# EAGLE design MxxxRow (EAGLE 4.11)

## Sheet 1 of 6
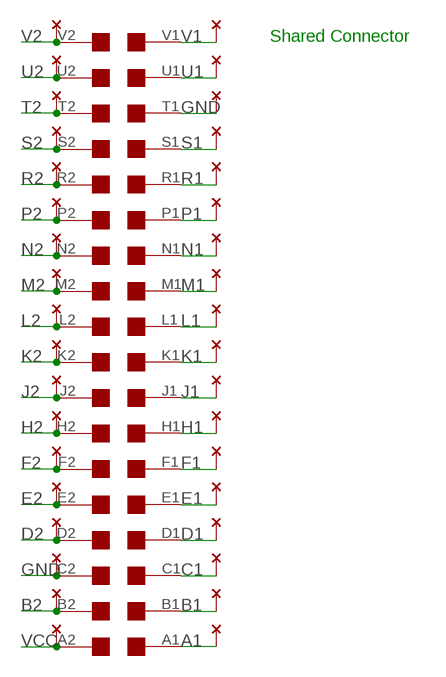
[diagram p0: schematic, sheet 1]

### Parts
U$1  EDGE-2  [EDGE-CON2]
U$4  THRU-HOLE2  [THRU-HOLEB]

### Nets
A1: U$1.A1 U$4.A2 ; also sheet 2,3,4,5,6
B1: U$1.B1 U$4.B2 ; also sheet 2,3,4,5,6
B2: U$1.B2 U$4.B1
C1: U$1.C1 U$4.C2 ; also sheet 2,3,4,5,6
D1: U$1.D1 U$4.D2 ; also sheet 2,3,4,5,6
D2: U$1.D2 U$4.D1 ; also sheet 2,3,4,5,6
E1: U$1.E1 U$4.E2 ; also sheet 2,3,4,5
E2: U$1.E2 U$4.E1 ; also sheet 2,3,4,5,6
F1: U$1.F1 U$4.F2 ; also sheet 2,3,4,5,6
F2: U$1.F2 U$4.F1 ; also sheet 2,3,4,5,6
GND [Power]: U$1.C2 U$1.T1 U$4.C1 U$4.T2 ; also sheet 2,3,4,5,6
H1: U$1.H1 U$4.H2 ; also sheet 2,3,4,5,6
H2: U$1.H2 U$4.H1 ; also sheet 2,3,4,5,6
J1: U$1.J1 U$4.J2 ; also sheet 2,3,4,5,6
J2: U$1.J2 U$4.J1 ; also sheet 2,3,4,5,6
K1: U$1.K1 U$4.K2 ; also sheet 2,3,4,5,6
K2: U$1.K2 U$4.K1 ; also sheet 2,3,4,5,6
L1: U$1.L1 U$4.L2 ; also sheet 2,3,4,5
L2: U$1.L2 U$4.L1 ; also sheet 2,3,4,5,6
M1: U$1.M1 U$4.M2 ; also sheet 2,3,4,5,6
M2: U$1.M2 U$4.M1 ; also sheet 2,3,4,5,6
N1: U$1.N1 U$4.N2 ; also sheet 2,3,4,5,6
N2: U$1.N2 U$4.N1 ; also sheet 2,3,4,5,6
P1: U$1.P1 U$4.P2 ; also sheet 2,3,4,5,6
P2: U$1.P2 U$4.P1 ; also sheet 2,3,4,5,6
R1: U$1.R1 U$4.R2 ; also sheet 2,3,4,5,6
R2: U$1.R2 U$4.R1 ; also sheet 2,3,4,5,6
S1: U$1.S1 U$4.S2 ; also sheet 2,3,4,5
S2: U$1.S2 U$4.S1 ; also sheet 2,3,4,5,6
T2: U$1.T2 U$4.T1 ; also sheet 2,3,4,5,6
U1: U$1.U1 U$4.U2 ; also sheet 2,3,4
U2: U$1.U2 U$4.U1 ; also sheet 2,3,4,5,6
V1: U$1.V1 U$4.V2 ; also sheet 2,3,4
V2: U$1.V2 U$4.V1 ; also sheet 2,3,4,5,6
VCC [Power]: U$1.A2 U$4.A1 ; also sheet 2,3,4,5,6

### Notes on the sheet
- Shared Connector

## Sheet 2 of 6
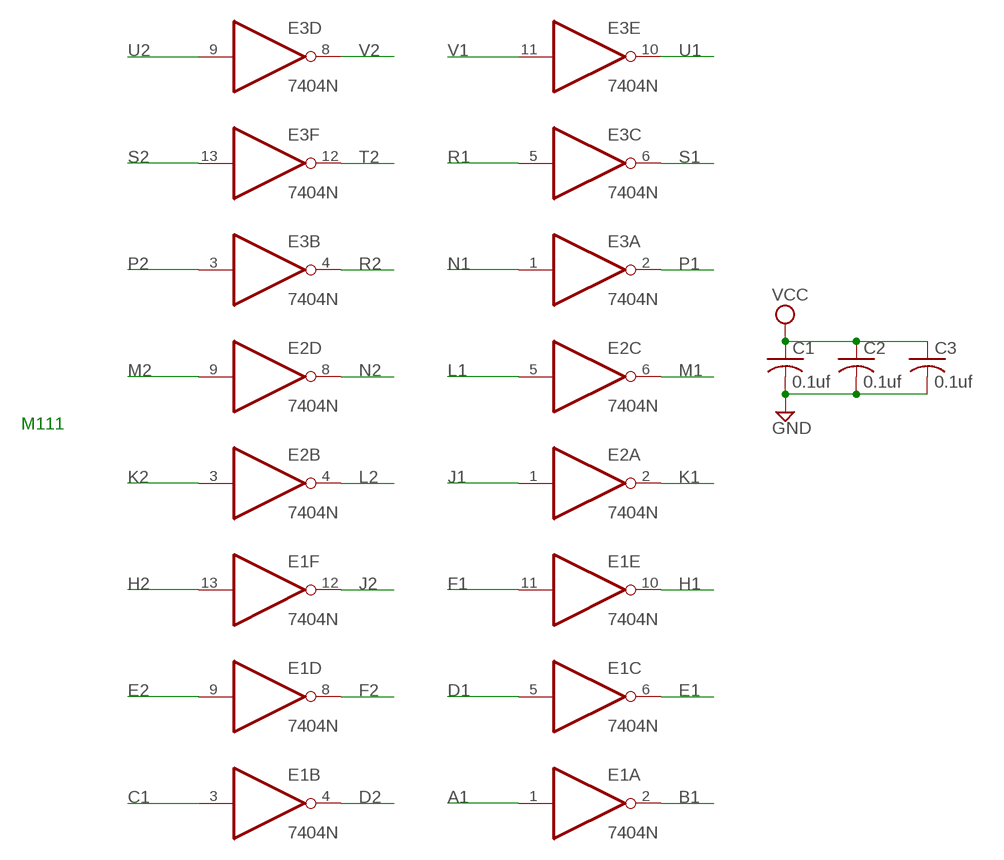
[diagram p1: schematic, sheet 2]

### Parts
C1  0.1uf  C-US050-025X075  [C050-025X075]
C2  0.1uf  C-US050-025X075  [C050-025X075]
C3  0.1uf  C-US050-025X075  [C050-025X075]
E1  7404N  [DIL14]
E2  7404N  [DIL14]
E3  7404N  [DIL14]

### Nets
A1: E1.1(A:I) ; also sheet 1,3,4,5,6
B1: E1.2(A:O) ; also sheet 1,3,4,5,6
C1: E1.3(B:I) ; also sheet 1,3,4,5,6
D1: E1.5(C:I) ; also sheet 1,3,4,5,6
D2: E1.4(B:O) ; also sheet 1,3,4,5,6
E1: E1.6(C:O) ; also sheet 1,3,4,5
E2: E1.9(D:I) ; also sheet 1,3,4,5,6
F1: E1.11(E:I) ; also sheet 1,3,4,5,6
F2: E1.8(D:O) ; also sheet 1,3,4,5,6
GND [Power]: C1.2 C2.2 C3.2 ; also sheet 1,3,4,5,6
H1: E1.10(E:O) ; also sheet 1,3,4,5,6
H2: E1.13(F:I) ; also sheet 1,3,4,5,6
J1: E2.1(A:I) ; also sheet 1,3,4,5,6
J2: E1.12(F:O) ; also sheet 1,3,4,5,6
K1: E2.2(A:O) ; also sheet 1,3,4,5,6
K2: E2.3(B:I) ; also sheet 1,3,4,5,6
L1: E2.5(C:I) ; also sheet 1,3,4,5
L2: E2.4(B:O) ; also sheet 1,3,4,5,6
M1: E2.6(C:O) ; also sheet 1,3,4,5,6
M2: E2.9(D:I) ; also sheet 1,3,4,5,6
N1: E3.1(A:I) ; also sheet 1,3,4,5,6
N2: E2.8(D:O) ; also sheet 1,3,4,5,6
P1: E3.2(A:O) ; also sheet 1,3,4,5,6
P2: E3.3(B:I) ; also sheet 1,3,4,5,6
R1: E3.5(C:I) ; also sheet 1,3,4,5,6
R2: E3.4(B:O) ; also sheet 1,3,4,5,6
S1: E3.6(C:O) ; also sheet 1,3,4,5
S2: E3.13(F:I) ; also sheet 1,3,4,5,6
T2: E3.12(F:O) ; also sheet 1,3,4,5,6
U1: E3.10(E:O) ; also sheet 1,3,4
U2: E3.9(D:I) ; also sheet 1,3,4,5,6
V1: E3.11(E:I) ; also sheet 1,3,4
V2: E3.8(D:O) ; also sheet 1,3,4,5,6
VCC [Power]: C1.1 C2.1 C3.1 ; also sheet 1,3,4,5,6
Unconnected: E2.10(E:O) E2.11(E:I) E2.12(F:O) E2.13(F:I)

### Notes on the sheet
- M111

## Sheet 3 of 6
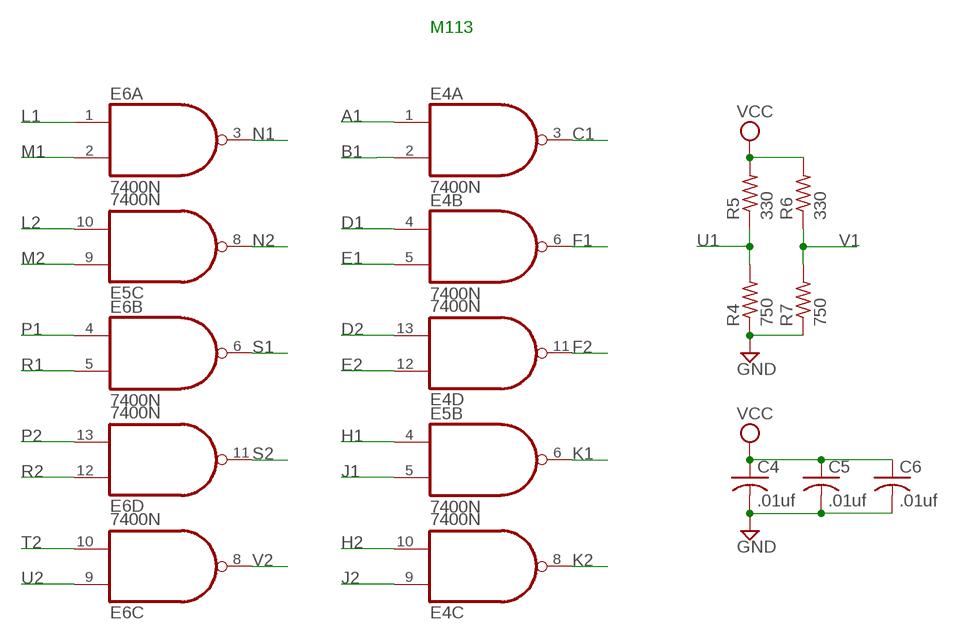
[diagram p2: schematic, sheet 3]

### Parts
C4  .01uf  C-US050-025X075  [C050-025X075]
C5  .01uf  C-US050-025X075  [C050-025X075]
C6  .01uf  C-US050-025X075  [C050-025X075]
E4  7400N  [DIL14]
E5  7400N  [DIL14]
E6  7400N  [DIL14]
R4  750  R-US_0207/10  [0207/10]
R5  330  R-US_0207/10  [0207/10]
R6  330  R-US_0207/10  [0207/10]
R7  750  R-US_0207/10  [0207/10]

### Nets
A1: E4.1(A:I0) ; also sheet 1,2,4,5,6
B1: E4.2(A:I1) ; also sheet 1,2,4,5,6
C1: E4.3(A:O) ; also sheet 1,2,4,5,6
D1: E4.4(B:I0) ; also sheet 1,2,4,5,6
D2: E4.13(D:I1) ; also sheet 1,2,4,5,6
E1: E4.5(B:I1) ; also sheet 1,2,4,5
E2: E4.12(D:I0) ; also sheet 1,2,4,5,6
F1: E4.6(B:O) ; also sheet 1,2,4,5,6
F2: E4.11(D:O) ; also sheet 1,2,4,5,6
GND [Power]: C4.2 C5.2 C6.2 R4.1 R7.1 ; also sheet 1,2,4,5,6
H1: E5.4(B:I0) ; also sheet 1,2,4,5,6
H2: E4.10(C:I1) ; also sheet 1,2,4,5,6
J1: E5.5(B:I1) ; also sheet 1,2,4,5,6
J2: E4.9(C:I0) ; also sheet 1,2,4,5,6
K1: E5.6(B:O) ; also sheet 1,2,4,5,6
K2: E4.8(C:O) ; also sheet 1,2,4,5,6
L1: E6.1(A:I0) ; also sheet 1,2,4,5
L2: E5.10(C:I1) ; also sheet 1,2,4,5,6
M1: E6.2(A:I1) ; also sheet 1,2,4,5,6
M2: E5.9(C:I0) ; also sheet 1,2,4,5,6
N1: E6.3(A:O) ; also sheet 1,2,4,5,6
N2: E5.8(C:O) ; also sheet 1,2,4,5,6
P1: E6.4(B:I0) ; also sheet 1,2,4,5,6
P2: E6.13(D:I1) ; also sheet 1,2,4,5,6
R1: E6.5(B:I1) ; also sheet 1,2,4,5,6
R2: E6.12(D:I0) ; also sheet 1,2,4,5,6
S1: E6.6(B:O) ; also sheet 1,2,4,5
S2: E6.11(D:O) ; also sheet 1,2,4,5,6
T2: E6.10(C:I1) ; also sheet 1,2,4,5,6
U1: R4.2 R5.1 ; also sheet 1,2,4
U2: E6.9(C:I0) ; also sheet 1,2,4,5,6
V1: R6.1 R7.2 ; also sheet 1,2,4
V2: E6.8(C:O) ; also sheet 1,2,4,5,6
VCC [Power]: C4.1 C5.1 C6.1 R5.2 R6.2 ; also sheet 1,2,4,5,6
Unconnected: E5.1(A:I0) E5.2(A:I1) E5.3(A:O) E5.11(D:O) E5.12(D:I0) E5.13(D:I1)

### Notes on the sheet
- M113

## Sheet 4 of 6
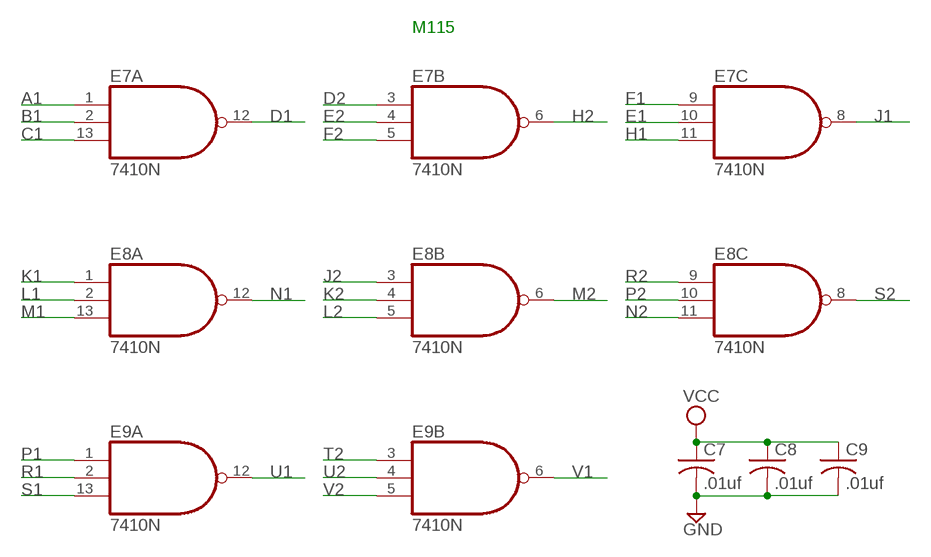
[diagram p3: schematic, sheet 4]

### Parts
C7  .01uf  C-US050-025X075  [C050-025X075]
C8  .01uf  C-US050-025X075  [C050-025X075]
C9  .01uf  C-US050-025X075  [C050-025X075]
E7  7410N  [DIL14]
E8  7410N  [DIL14]
E9  7410N  [DIL14]

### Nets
A1: E7.1(A:I0) ; also sheet 1,2,3,5,6
B1: E7.2(A:I1) ; also sheet 1,2,3,5,6
C1: E7.13(A:I2) ; also sheet 1,2,3,5,6
D1: E7.12(A:O) ; also sheet 1,2,3,5,6
D2: E7.3(B:I0) ; also sheet 1,2,3,5,6
E1: E7.10(C:I1) ; also sheet 1,2,3,5
E2: E7.4(B:I1) ; also sheet 1,2,3,5,6
F1: E7.9(C:I0) ; also sheet 1,2,3,5,6
F2: E7.5(B:I2) ; also sheet 1,2,3,5,6
GND [Power]: C7.2 C8.2 C9.2 ; also sheet 1,2,3,5,6
H1: E7.11(C:I2) ; also sheet 1,2,3,5,6
H2: E7.6(B:O) ; also sheet 1,2,3,5,6
J1: E7.8(C:O) ; also sheet 1,2,3,5,6
J2: E8.3(B:I0) ; also sheet 1,2,3,5,6
K1: E8.1(A:I0) ; also sheet 1,2,3,5,6
K2: E8.4(B:I1) ; also sheet 1,2,3,5,6
L1: E8.2(A:I1) ; also sheet 1,2,3,5
L2: E8.5(B:I2) ; also sheet 1,2,3,5,6
M1: E8.13(A:I2) ; also sheet 1,2,3,5,6
M2: E8.6(B:O) ; also sheet 1,2,3,5,6
N1: E8.12(A:O) ; also sheet 1,2,3,5,6
N2: E8.11(C:I2) ; also sheet 1,2,3,5,6
P1: E9.1(A:I0) ; also sheet 1,2,3,5,6
P2: E8.10(C:I1) ; also sheet 1,2,3,5,6
R1: E9.2(A:I1) ; also sheet 1,2,3,5,6
R2: E8.9(C:I0) ; also sheet 1,2,3,5,6
S1: E9.13(A:I2) ; also sheet 1,2,3,5
S2: E8.8(C:O) ; also sheet 1,2,3,5,6
T2: E9.3(B:I0) ; also sheet 1,2,3,5,6
U1: E9.12(A:O) ; also sheet 1,2,3
U2: E9.4(B:I1) ; also sheet 1,2,3,5,6
V1: E9.6(B:O) ; also sheet 1,2,3
V2: E9.5(B:I2) ; also sheet 1,2,3,5,6
VCC [Power]: C7.1 C8.1 C9.1 ; also sheet 1,2,3,5,6
Unconnected: E9.8(C:O) E9.9(C:I0) E9.10(C:I1) E9.11(C:I2)

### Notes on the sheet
- M115

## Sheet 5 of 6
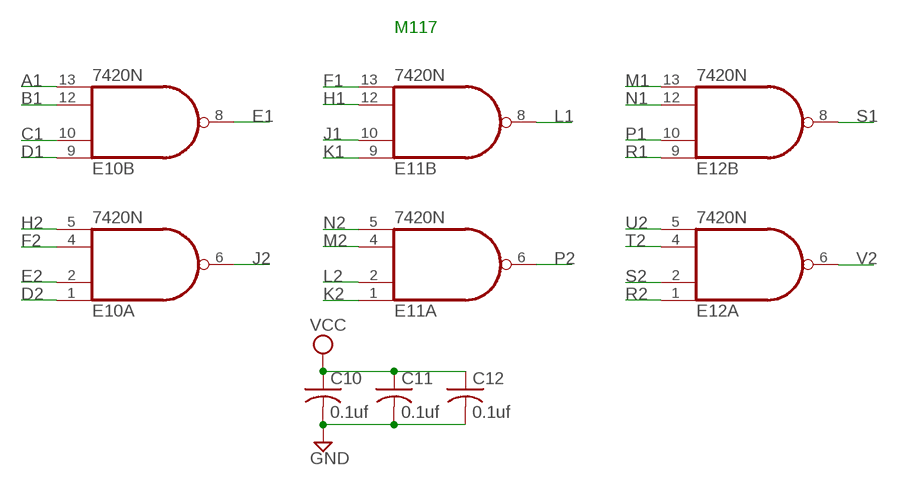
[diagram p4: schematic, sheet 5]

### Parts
C10  0.1uf  C-US050-025X075  [C050-025X075]
C11  0.1uf  C-US050-025X075  [C050-025X075]
C12  0.1uf  C-US050-025X075  [C050-025X075]
E10  7420N  74S20N  [DIL14]
E11  7420N  74S20N  [DIL14]
E12  7420N  74S20N  [DIL14]

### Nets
A1: E10.13(B:I3) ; also sheet 1,2,3,4,6
B1: E10.12(B:I2) ; also sheet 1,2,3,4,6
C1: E10.10(B:I1) ; also sheet 1,2,3,4,6
D1: E10.9(B:I0) ; also sheet 1,2,3,4,6
D2: E10.1(A:I0) ; also sheet 1,2,3,4,6
E1: E10.8(B:O) ; also sheet 1,2,3,4
E2: E10.2(A:I1) ; also sheet 1,2,3,4,6
F1: E11.13(B:I3) ; also sheet 1,2,3,4,6
F2: E10.4(A:I2) ; also sheet 1,2,3,4,6
GND [Power]: C10.2 C11.2 C12.2 ; also sheet 1,2,3,4,6
H1: E11.12(B:I2) ; also sheet 1,2,3,4,6
H2: E10.5(A:I3) ; also sheet 1,2,3,4,6
J1: E11.10(B:I1) ; also sheet 1,2,3,4,6
J2: E10.6(A:O) ; also sheet 1,2,3,4,6
K1: E11.9(B:I0) ; also sheet 1,2,3,4,6
K2: E11.1(A:I0) ; also sheet 1,2,3,4,6
L1: E11.8(B:O) ; also sheet 1,2,3,4
L2: E11.2(A:I1) ; also sheet 1,2,3,4,6
M1: E12.13(B:I3) ; also sheet 1,2,3,4,6
M2: E11.4(A:I2) ; also sheet 1,2,3,4,6
N1: E12.12(B:I2) ; also sheet 1,2,3,4,6
N2: E11.5(A:I3) ; also sheet 1,2,3,4,6
P1: E12.10(B:I1) ; also sheet 1,2,3,4,6
P2: E11.6(A:O) ; also sheet 1,2,3,4,6
R1: E12.9(B:I0) ; also sheet 1,2,3,4,6
R2: E12.1(A:I0) ; also sheet 1,2,3,4,6
S1: E12.8(B:O) ; also sheet 1,2,3,4
S2: E12.2(A:I1) ; also sheet 1,2,3,4,6
T2: E12.4(A:I2) ; also sheet 1,2,3,4,6
U2: E12.5(A:I3) ; also sheet 1,2,3,4,6
V2: E12.6(A:O) ; also sheet 1,2,3,4,6
VCC [Power]: C10.1 C11.1 C12.1 ; also sheet 1,2,3,4,6

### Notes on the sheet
- M117

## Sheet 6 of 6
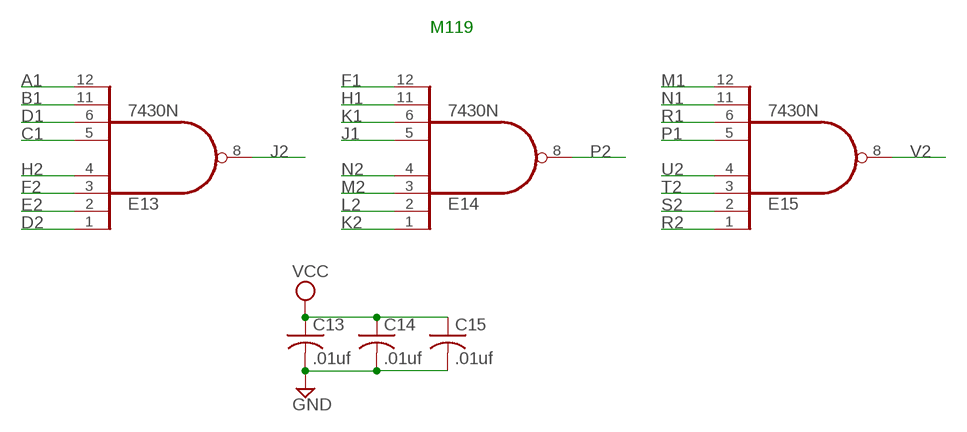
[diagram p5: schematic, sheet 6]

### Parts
C13  .01uf  C-US050-025X075  [C050-025X075]
C14  .01uf  C-US050-025X075  [C050-025X075]
C15  .01uf  C-US050-025X075  [C050-025X075]
E13  7430N  [DIL14]
E14  7430N  [DIL14]
E15  7430N  [DIL14]

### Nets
A1: E13.12(I7) ; also sheet 1,2,3,4,5
B1: E13.11(I6) ; also sheet 1,2,3,4,5
C1: E13.5(I4) ; also sheet 1,2,3,4,5
D1: E13.6(I5) ; also sheet 1,2,3,4,5
D2: E13.1(I0) ; also sheet 1,2,3,4,5
E2: E13.2(I1) ; also sheet 1,2,3,4,5
F1: E14.12(I7) ; also sheet 1,2,3,4,5
F2: E13.3(I2) ; also sheet 1,2,3,4,5
GND [Power]: C13.2 C14.2 C15.2 ; also sheet 1,2,3,4,5
H1: E14.11(I6) ; also sheet 1,2,3,4,5
H2: E13.4(I3) ; also sheet 1,2,3,4,5
J1: E14.5(I4) ; also sheet 1,2,3,4,5
J2: E13.8(O) ; also sheet 1,2,3,4,5
K1: E14.6(I5) ; also sheet 1,2,3,4,5
K2: E14.1(I0) ; also sheet 1,2,3,4,5
L2: E14.2(I1) ; also sheet 1,2,3,4,5
M1: E15.12(I7) ; also sheet 1,2,3,4,5
M2: E14.3(I2) ; also sheet 1,2,3,4,5
N1: E15.11(I6) ; also sheet 1,2,3,4,5
N2: E14.4(I3) ; also sheet 1,2,3,4,5
P1: E15.5(I4) ; also sheet 1,2,3,4,5
P2: E14.8(O) ; also sheet 1,2,3,4,5
R1: E15.6(I5) ; also sheet 1,2,3,4,5
R2: E15.1(I0) ; also sheet 1,2,3,4,5
S2: E15.2(I1) ; also sheet 1,2,3,4,5
T2: E15.3(I2) ; also sheet 1,2,3,4,5
U2: E15.4(I3) ; also sheet 1,2,3,4,5
V2: E15.8(O) ; also sheet 1,2,3,4,5
VCC [Power]: C13.1 C14.1 C15.1 ; also sheet 1,2,3,4,5

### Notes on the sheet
- M119

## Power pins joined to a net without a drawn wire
GND: E1.7(P:GND) E2.7(P:GND) E3.7(P:GND) E4.7(P:GND) E5.7(P:GND) E6.7(P:GND) E7.7(P:GND) E8.7(P:GND) E9.7(P:GND) E10.7(P:GND) E11.7(P:GND) E12.7(P:GND) E13.7(GND) E14.7(GND) E15.7(GND)
VCC: E1.14(P:VCC) E2.14(P:VCC) E3.14(P:VCC) E4.14(P:VCC) E5.14(P:VCC) E6.14(P:VCC) E7.14(P:VCC) E8.14(P:VCC) E9.14(P:VCC) E10.14(P:VCC) E11.14(P:VCC) E12.14(P:VCC) E13.14(VCC) E14.14(VCC) E15.14(VCC)

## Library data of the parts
C1-C15 = rcl:C-US: CAPACITOR, American symbol
E1-E3 = 74xx-us:74*04: Hex INVERTER
E4-E6 = 74xx-us:74*00: Quad 2-input NAND gate
E7-E9 = 74xx-us:74*10: Triple 3-input NAND gate
E10-E12 = 74xx-us:74*20: Dual 4-input NAND gate
E13-E15 = 74xx-us:74*30: 8-input NAND gate
R4-R7 = rcl:R-US_: RESISTOR, American symbol
U$1 = dec-con:EDGE-2: Double-Sided DEC edge connector.
U$4 = dec-con:THRU-HOLE2: Thru-Hole addition to double-sided edge connector.

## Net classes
1 Power: width 0.381 mm

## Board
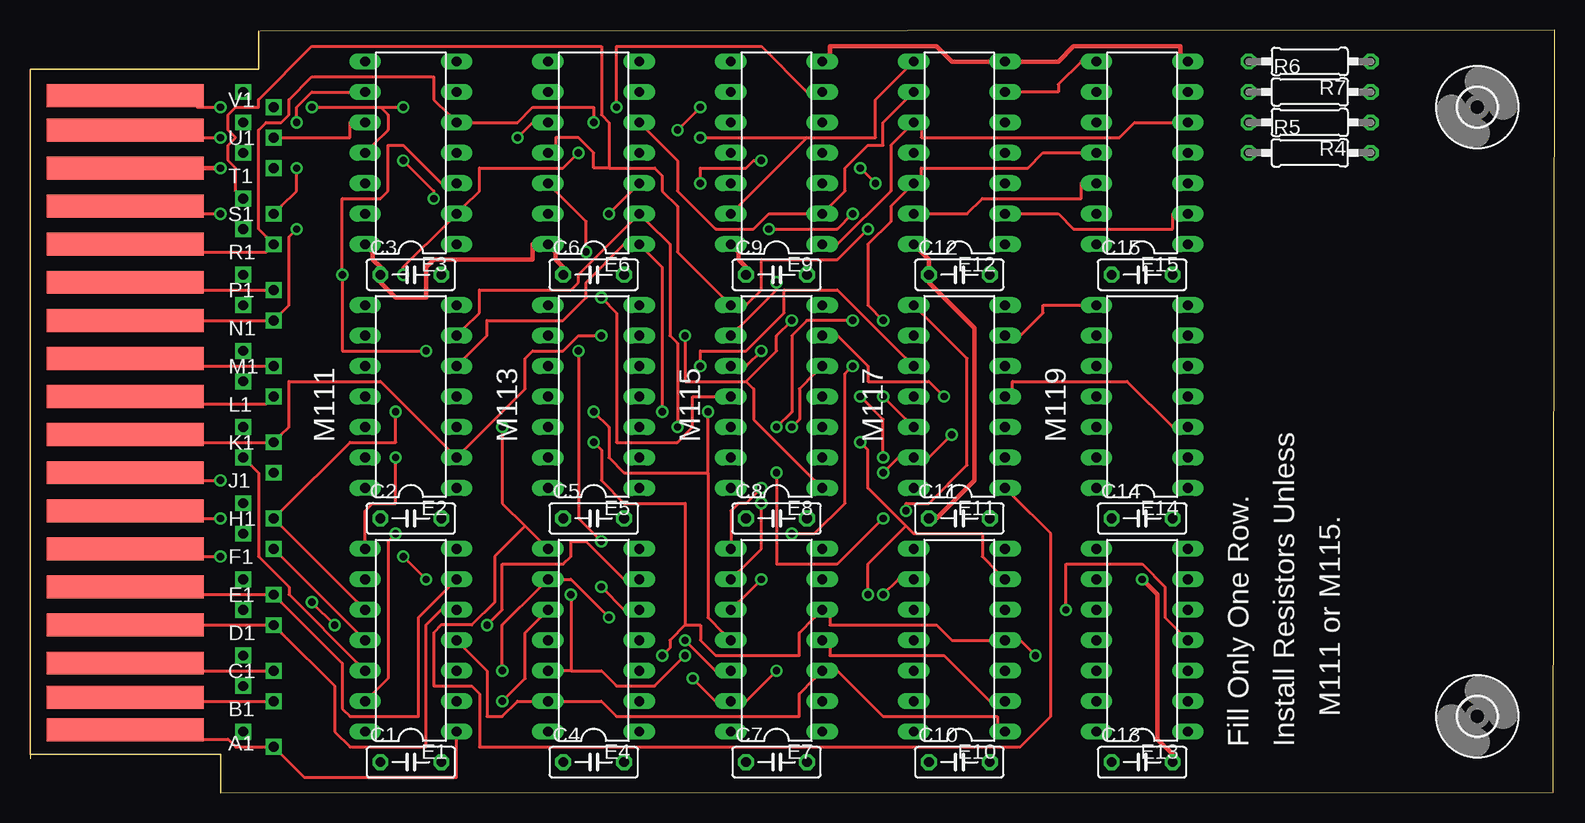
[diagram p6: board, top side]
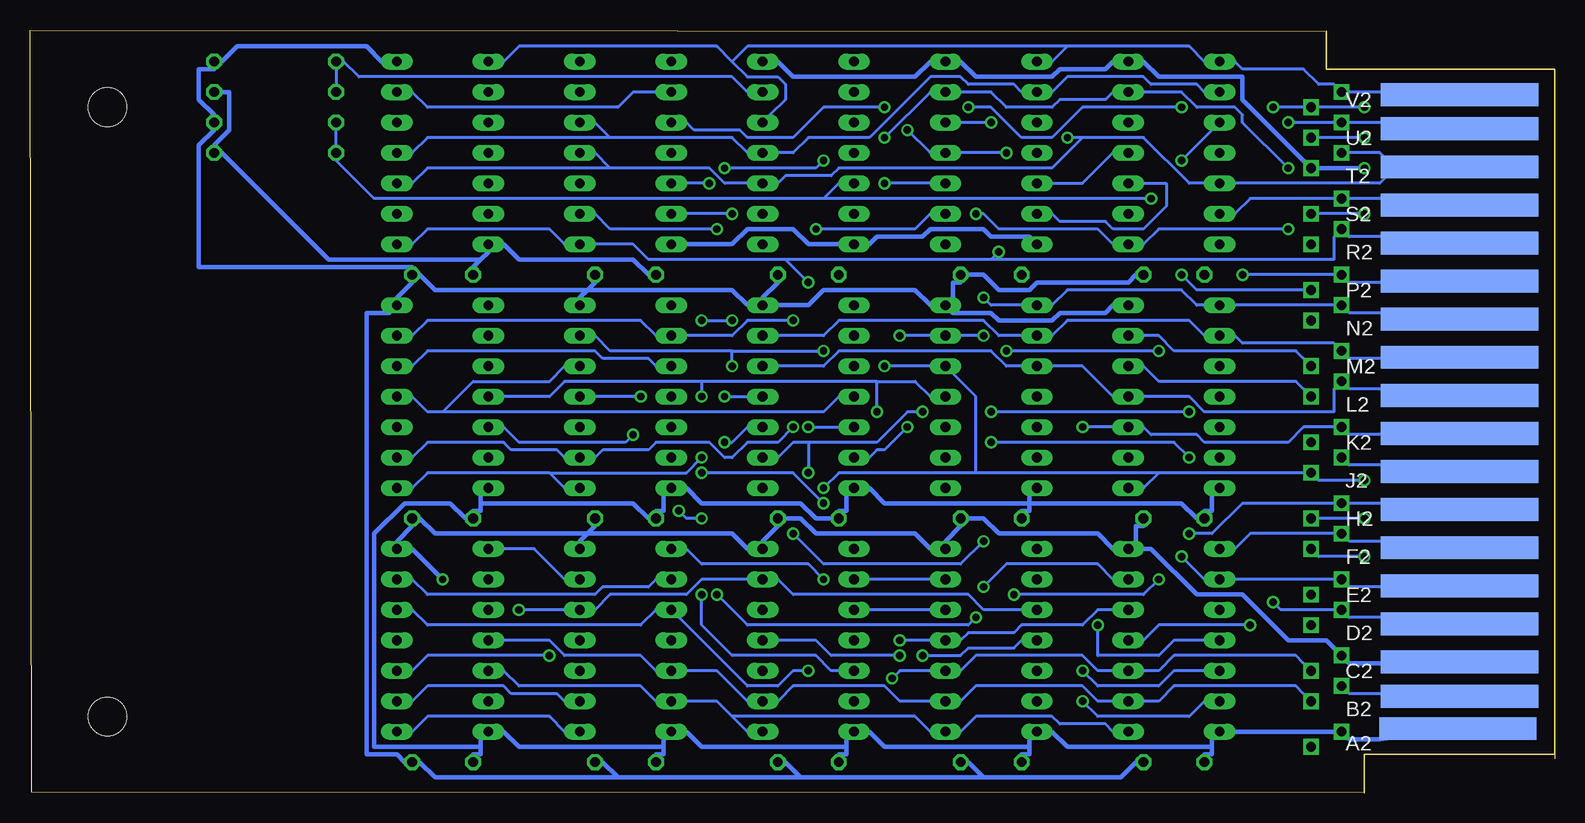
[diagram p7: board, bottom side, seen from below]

Size 127.11 x 63.59 mm. Coordinates in mm from the lower left corner, seen from the top.
Outline: 15.88,0 126.98,0.04 127.11,63.59 19.18,63.5
Outline: 0.01,59.65 0.01,2.83
Copper layers (1*16): Top 0.035mm / dielectric 1.5mm / Bottom 0.035mm
Design rules "10mils": minimum track width 10mil, minimum drill 24mil, track to track 10mil, track to pad 10mil, pad to pad 10mil, via to via 10mil, smd to smd 10mil, copper to edge 40mil, drill to drill 10mil, minimum pad ring 10mil, minimum via ring 8mil, stop-mask expansion 0mil, vias tented up to drill 0mil, thermal gap 10mil

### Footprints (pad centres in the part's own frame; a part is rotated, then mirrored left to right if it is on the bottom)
C050-025X075 = drill 0.813 octagon: 1 -2.54,0; 2 2.54,0
DIL14 = drill 0.813 long: 1 -7.62,-3.81; 2 -5.08,-3.81; 3 -2.54,-3.81; 4 0,-3.81; 5 2.54,-3.81; 6 5.08,-3.81; 7 7.62,-3.81; 8 7.62,3.81; 9 5.08,3.81; 10 2.54,3.81; 11 0,3.81; 12 -2.54,3.81; 13 -5.08,3.81; 14 -7.62,3.81
0207/10 = drill 0.813 octagon: 1 -5.08,0; 2 5.08,0
EDGE-CON2 = smd 13.106 x 1.905: A1 7.938,5.239; B1 7.938,7.938; C1 7.938,10.795; D1 7.938,13.97; E1 7.938,17.145; F1 7.938,20.32; H1 7.938,23.495; J1 7.938,26.67; K1 7.938,29.845; L1 7.938,33.02; M1 7.938,36.195; N1 7.938,39.37; P1 7.938,42.545; R1 7.938,45.72; S1 7.938,48.895; T1 7.938,52.07; U1 7.938,55.245; V1 7.938,58.102 | smd 13.106 x 1.905 bottom: A2 8.096,5.34; B2 7.938,8.039; C2 7.938,10.897; D2 7.938,14.072; E2 7.938,17.247; F2 7.938,20.422; H2 7.938,23.597; J2 7.938,26.772; K2 7.938,29.947; L2 7.938,33.122; M2 7.938,36.297; N2 7.938,39.472; P2 7.938,42.647; R2 7.938,45.822; S2 7.938,48.997; T2 7.938,52.172; U2 7.938,55.347; V2 7.938,58.204
3,2 = hole 3.2: 0,0
THRU-HOLEB = drill 0.813 square: A1 17.78,5.08; A2 20.32,3.81; B1 17.78,8.89; B2 20.32,7.62; C1 17.78,11.43; C2 20.32,10.16; D1 17.78,15.24; D2 20.32,13.97; E1 17.78,17.78; E2 20.32,16.51; F1 17.78,21.59; F2 20.32,20.32; H1 17.78,24.13; H2 20.32,22.86; J1 17.78,27.94; J2 20.32,26.67; K1 17.78,30.48; K2 20.32,29.21; L1 17.78,34.29; L2 20.32,33.02; M1 17.78,36.83; M2 20.32,35.56; N1 17.78,40.64; N2 20.32,39.37; P1 17.78,43.18; P2 20.32,41.91; R1 17.78,46.99; R2 20.32,45.72; S1 17.78,49.53; S2 20.32,48.26; T1 17.78,53.34; T2 20.32,52.07; U1 17.78,55.88; U2 20.32,54.61; V1 17.78,58.42; V2 20.32,57.15

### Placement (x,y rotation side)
C1  31.75,2.54 0 top
C2  31.75,22.86 0 top
C3  31.75,43.18 0 top
C4  46.99,2.54 0 top
C5  46.99,22.86 0 top
C6  46.99,43.18 0 top
C7  62.23,2.54 0 top
C8  62.23,22.86 0 top
C9  62.23,43.18 0 top
C10  77.47,2.54 0 top
C11  77.47,22.86 0 top
C12  77.47,43.18 0 top
C13  92.71,2.54 0 top
C14  92.71,22.86 0 top
C15  92.71,43.18 0 top
E1  31.75,12.7 90 top
E2  31.75,33.02 90 top
E3  31.75,53.34 90 top
E4  46.99,12.7 90 top
E5  46.99,33.02 90 top
E6  46.99,53.34 90 top
E7  62.23,12.7 90 top
E8  62.23,33.02 90 top
E9  62.23,53.34 90 top
E10  77.47,12.7 90 top
E11  77.47,33.02 90 top
E12  77.47,53.34 90 top
E13  92.71,12.7 90 top
E14  92.71,33.02 90 top
E15  92.71,53.34 90 top
R4  106.68,55.88 180 top
R5  106.68,53.34 0 top
R6  106.68,58.42 0 top
R7  106.68,60.96 180 top
U$1  0,0 0 top
U$2  [3,2]  120.65,6.35 0 top
U$3  [3,2]  120.65,57.15 0 top
U$4  0,0 0 top

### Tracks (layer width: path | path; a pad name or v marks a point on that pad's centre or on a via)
A1
  Top 0.254: U$1.A1 13.97,4.45 16.51,4.45 17.14,3.81 19.68,3.81 U$4.A2 20.95,3.17 22.86,1.27 35.56,1.27 35.56,4.45 E1.1
  Bottom 0.254: E1.1 36.83,5.08 37.47,5.71 41.27,5.71 41.91,6.35 48.26,6.35 49.53,5.08 E4.1 52.07,5.08 53.34,6.35 68.58,6.35 | 68.58,6.35 69.85,7.62 72.39,7.62 E10.13 74.93,7.62 76.2,8.89 86.36,8.89 87.63,10.16 E13.12 | 68.58,6.35 67.31,5.08 E7.1
B1
  Top 0.254: U$1.B1 13.97,7.62 19.68,7.62 U$4.B2
  Bottom 0.254: E13.11 87.63,12.7 83.82,12.7 82.55,11.43 76.2,11.43 74.93,10.16 E10.12 72.39,10.16 69.85,10.16 67.31,7.62 E7.2 64.77,7.62 63.5,8.89 55.88,8.89 54.61,7.62 52.07,7.62 E4.2 49.53,7.62 48.26,8.89 39.37,8.89 38.1,7.62 36.83,7.62 E1.2 34.29,7.62 33.02,7.62 31.75,8.89 21.59,8.89 20.95,8.26 U$4.B2
B2
  Bottom 0.254: U$4.B1 17.14,8.26 13.97,8.26 U$1.B2
C1  (via drill 0.61)
  Top 0.254: v55.24,9.53 57.15,7.62 E7.13 59.69,7.62 v62.23,10.16 | U$1.C1 13.97,10.16 19.68,10.16 U$4.C2
  Bottom 0.254: E13.5 95.25,15.24 93.98,13.97 76.2,13.97 74.93,15.24 E10.10 73.03,14.61 67.31,8.89 64.77,8.89 63.5,10.16 v62.23,10.16 | U$4.C2 20.95,10.79 21.59,11.43 31.75,11.43 33.02,10.16 34.29,10.16 E1.3 36.83,10.16 38.1,10.16 39.37,11.43 48.26,11.43 49.53,10.16 E4.3 52.07,10.16 54.61,10.16 v55.24,9.53
D1  (via drill 0.61)
  Top 0.254: U$1.D1 13.97,13.97 19.68,13.97 U$4.D2 20.95,13.34 25.4,8.89 25.4,5.08 26.67,3.81 33.02,3.81 33.02,13.97 34.29,15.24 E1.5 | v54.61,12.7 57.15,10.16 E7.12 | v71.12,16.51 72.39,17.78 E10.9
  Bottom 0.254: E10.9 74.93,17.78 75.56,17.14 79.38,17.14 80.01,16.51 93.98,16.51 95.25,17.78 E13.6 | E1.5 36.83,15.24 38.1,15.24 39.37,13.97 44.45,13.97 45.09,13.34 48.9,13.34 49.53,12.7 E4.4 52.07,12.7 v54.61,12.7 | v71.12,16.51 71.12,13.97 68.58,11.43 61.59,11.43 60.33,10.16 59.69,10.16 E7.12
D2  (via drill 0.61)
  Top 0.254: E1.4 36.2,12.06 38.1,10.16 38.1,6.35 39.37,6.35 40.64,7.62 41.91,7.62 E4.13 44.45,7.62 47.62,7.62 48.9,6.35 64.14,6.35 64.14,8.26 65.41,9.53 E7.3 67.31,10.16 71.12,6.35 80.64,6.35 80.64,5.71 E10.1 | v23.5,15.88 v25.4,13.97
  Bottom 0.254: U$1.D2 13.97,14.61 17.14,14.61 U$4.D1 18.41,15.24 22.86,15.24 v23.5,15.88 | E10.1 82.55,5.08 83.82,6.35 93.98,6.35 95.25,5.08 E13.1 | v25.4,13.97 33.02,13.97 34.29,12.7 E1.4
E1  (via drill 0.61)
  Top 0.254: U$1.E1 13.97,16.51 19.68,16.51 U$4.E2 20.95,15.88 26.04,10.79 26.04,6.99 26.67,6.35 32.38,6.35 32.38,14.61 34.92,17.14 E1.6 | v47.62,17.14 49.53,15.24 E4.5 | v60.96,17.78 59.05,15.88 E7.10
  Bottom 0.254: E4.5 52.07,15.24 57.15,15.24 E7.10 | v47.62,17.14 45.72,19.05 38.1,19.05 36.83,17.78 E1.6 | v60.96,17.78 62.23,19.05 71.12,19.05 72.39,20.32 E10.8
E2  (via drill 0.61)
  Top 0.254: 45.09,10.16 47.62,10.16 48.9,8.89 52.07,8.89 v54.61,11.43 | 45.09,10.16 44.45,10.16 E4.12 | E10.2 80.01,7.62 76.2,11.43 66.67,11.43 66.67,12.06 E7.4 | v31.11,19.68 v33.02,17.78 | v45.09,16.51 45.09,10.16
  Bottom 0.254: U$1.E2 13.97,17.14 17.14,17.14 U$4.E1 18.41,17.78 26.67,17.78 E1.9 29.21,17.78 v31.11,19.68 | E10.2 82.55,7.62 83.19,8.26 87,8.26 87.63,8.89 93.98,8.89 95.25,7.62 E13.2 | v54.61,11.43 60.33,11.43 61.59,12.7 64.77,12.7 E7.4 | v33.02,17.78 34.29,16.51 v45.09,16.51
F1  (via drill 0.61)
  Top 0.254: v76.83,29.84 74.93,27.94 E11.13 72.39,27.94 v71.12,26.67 | U$4.F2 20.95,19.68 27.3,13.34 E1.11 | v38.1,13.97 39.37,15.24 39.37,19.05 44.45,19.05 45.09,19.68 45.09,20.95 46.35,20.95 49.53,17.78 E4.6 | v60.96,24.13 60.96,20.32 59.05,18.41 E7.9 | v15.88,19.68 13.97,19.68 U$1.F1
  Bottom 0.254: v76.83,29.84 77.47,29.21 86.36,29.21 87.63,30.48 E14.12 | E4.6 52.07,17.78 57.15,17.78 E7.9 | v38.1,13.97 38.1,11.43 33.02,11.43 31.75,12.7 29.21,12.7 E1.11 | v71.12,26.67 63.5,26.67 v60.96,24.13 | v15.88,19.68 19.68,19.68 U$4.F2
F2  (via drill 0.61)
  Top 0.254: v52.7,11.43 53.34,12.06 53.34,12.7 54.61,13.97 | 54.61,13.97 55.88,13.97 55.88,12.7 57.15,11.43 64.14,11.43 64.14,13.34 65.41,14.61 E7.5 66.67,14.61 66.67,13.97 75.56,13.97 76.83,12.7 80.01,12.7 E10.4 82.55,12.7 v83.82,11.43 | v30.48,27.94 30.48,24.13 28.57,24.13 27.94,23.5 27.94,20.95 E1.8 | v46.99,29.21 47.62,28.57 47.62,26.04 49.53,24.13 54.61,24.13 54.61,13.97
  Bottom 0.254: U$1.F2 13.97,20.95 17.14,20.95 U$4.F1 18.41,21.59 25.4,21.59 26.67,20.32 E1.8 | v52.7,11.43 49.53,11.43 48.9,12.06 45.09,12.06 44.45,12.7 E4.11 | v83.82,11.43 93.98,11.43 95.25,10.16 E13.3 | v30.48,27.94 31.75,29.21 v46.99,29.21
GND  (via drill 0.61)
  Top 0.381: E9.7 66.67,61.59 66.67,62.23 75.56,62.23 76.83,60.96 80.01,60.96 E12.7 82.55,60.96 85.72,60.96 87,62.23 95.89,62.23 95.89,61.59 E15.7 | v15.88,52.07 13.97,52.07 U$1.T1 | v92.71,17.78 93.98,16.51 93.98,4.45 95.25,3.17 C13.2
  Bottom 0.381: U$1.C2 13.97,10.79 17.14,10.79 U$4.C1 18.41,12.06 19.05,12.7 22.23,12.7 26.04,16.51 29.84,16.51 33.66,20.32 34.29,20.32 E1.7 | E1.7 34.92,20.95 34.92,22.23 34.29,22.23 C2.2 | E1.7 36.83,20.32 38.1,21.59 46.35,21.59 47.62,22.86 48.9,22.86 C5.2 49.53,22.23 50.8,20.95 E4.7 52.07,20.32 53.34,21.59 61.59,21.59 62.87,22.86 64.14,22.86 C8.2 64.77,22.23 66.04,20.95 E7.7 67.31,20.32 68.58,21.59 80.64,21.59 | 80.64,21.59 81.28,20.95 E10.7 | 80.64,21.59 80.01,22.23 C11.2 | 80.64,21.59 93.34,21.59 94.61,22.86 C14.2 95.25,22.23 96.52,20.95 E13.7 95.25,20.32 v92.71,17.78 | E9.7 64.77,60.96 63.5,59.69 53.34,59.69 52.07,60.96 E6.7 49.53,60.96 48.26,59.69 41.91,59.69 41.27,60.33 37.47,60.33 36.83,60.96 E3.7 34.29,60.96 33.02,59.69 26.04,59.69 26.04,57.78 20.95,52.7 U$4.T2 19.68,52.07 v15.88,52.07 | 47.62,1.27 36.2,1.27 34.92,2.54 C1.2 | 47.62,1.27 48.9,2.54 C4.2 | 62.87,1.27 64.14,2.54 C7.2 | 62.87,1.27 47.62,1.27 | 78.11,1.27 79.38,2.54 C10.2 | 78.11,1.27 62.87,1.27 | 78.11,1.27 93.34,1.27 94.61,2.54 C13.2 95.89,2.54 96.52,3.17 99.06,3.17 99.06,40.01 97.16,40.01 E14.7 96.52,41.27 95.25,42.55 C15.2 | E15.7 97.79,60.96 99.06,62.23 109.86,62.23 111.12,60.96 R7.1 111.76,60.33 113.03,60.33 113.03,57.78 111.76,56.52 R4.1 111.76,55.24 113.03,53.98 113.03,43.81 95.25,43.81 C15.2 | E2.7 36.83,40.64 37.47,40.01 41.27,40.01 41.91,39.37 46.35,39.37 46.99,40.01 50.16,40.01 E5.7 | C3.2 34.92,43.18 35.56,42.55 43.18,42.55 43.81,41.91 46.35,41.91 47.62,43.18 48.9,43.18 C6.2 49.53,42.55 50.16,42.55 50.16,41.27 E5.7 | C9.2 64.77,42.55 66.04,41.27 E8.7 | 80.64,41.91 81.28,41.27 E11.7
  Bottom 0.381: 80.64,41.91 80.01,42.55 C12.2 | 80.64,41.91 68.58,41.91 67.31,40.64 E8.7 | 80.64,41.91 93.34,41.91 94.61,43.18 C15.2 | E5.7 52.07,40.64 53.34,41.91 60.96,41.91 62.23,40.64 64.77,40.64 E8.7
H1  (via drill 0.61)
  Top 0.254: E1.10 27.3,15.88 20.95,22.23 U$4.H2 20.95,23.5 26.67,29.21 30.48,29.21 v30.48,31.75 | v15.88,22.86 13.97,22.86 U$1.H1 | 56.52,26.67 v56.52,31.75 | 56.52,26.67 56.52,14.61 57.78,13.34 E7.11 | v71.12,33.02 73.03,31.11 E11.12 | v46.99,31.75 48.26,30.48 48.26,27.94 49.53,26.67 56.52,26.67
  Bottom 0.254: v15.88,22.86 19.68,22.86 U$4.H2 | 71.12,34.29 82.55,34.29 83.82,33.02 87.63,33.02 E14.11 | 56.52,34.29 71.12,34.29 | 56.52,34.29 53.34,34.29 52.07,33.02 E5.4 | v56.52,31.75 56.52,34.29 | 71.12,34.29 v71.12,33.02 | v30.48,31.75 v46.99,31.75
H2  (via drill 0.61)
  Top 0.254: v39.37,7.62 41.27,9.53 41.27,13.34 42.55,14.61 E4.10 | v86.36,15.24 86.36,19.05 92.71,19.05 94.61,17.14 94.61,14.61 95.89,13.34 E13.4 | v30.48,21.59 29.84,20.95 29.84,9.53 28.57,8.26 E1.13
  Bottom 0.254: U$1.H2 13.97,24.13 17.14,24.13 U$4.H1 18.41,24.13 26.04,24.13 28.57,21.59 v30.48,21.59 | v39.37,7.62 38.1,6.35 30.48,6.35 29.21,7.62 E1.13 | v86.36,15.24 82.55,15.24 E10.5 80.01,15.24 78.74,16.51 72.39,16.51 71.12,17.78 67.31,17.78 E7.6 64.77,17.78 63.5,16.51 48.9,16.51 47.62,15.24 44.45,15.24 E4.10
J1  (via drill 0.61)
  Top 0.254: v60.96,25.4 59.69,24.13 59.05,24.13 58.42,23.5 58.42,20.95 E7.8 | v55.88,35.56 55.88,36.83 59.69,36.83 62.87,40.01 62.87,41.91 67.31,41.91 73.03,36.2 E11.10 | v15.88,26.04 13.97,26.04 U$1.J1
  Bottom 0.254: E11.10 74.93,35.56 75.56,36.2 79.38,36.2 80.01,36.83 93.98,36.83 95.25,35.56 E14.5 | 33.02,26.67 20.95,26.67 U$4.J2 19.68,26.04 v15.88,26.04 | 33.02,26.67 34.29,25.4 E2.1 | 48.26,26.67 48.26,33.02 50.16,34.92 E5.5 52.07,35.56 v55.88,35.56 | 33.02,26.67 48.26,26.67 | v60.96,25.4 59.69,26.67 48.26,26.67
J2  (via drill 0.61)
  Top 0.254: v69.22,29.21 69.85,28.57 69.85,25.4 73.03,22.23 | 73.03,22.23 73.66,21.59 79.38,21.59 79.38,19.68 80.64,18.41 E10.6 | E1.12 27.3,10.79 21.59,16.51 21.59,17.14 19.05,19.68 19.05,26.67 18.41,27.3 U$4.J1 | v39.37,10.16 39.37,13.97 42.55,17.14 E4.9 44.45,17.78 45.09,17.78 v48.26,14.61 | 73.03,22.23 69.85,19.05 v69.85,16.51
  Bottom 0.254: E10.6 82.55,17.78 85.09,20.32 87.63,20.32 E13.8 | v69.22,29.21 68.58,29.21 67.31,30.48 E8.3 | U$4.J1 17.14,27.3 13.97,27.3 U$1.J2 | v39.37,10.16 38.1,8.89 33.02,8.89 31.75,10.16 29.21,10.16 E1.12 | v69.85,16.51 67.31,13.97 48.9,13.97 v48.26,14.61
K1  (via drill 0.61)
  Top 0.254: U$1.K1 13.97,29.21 19.68,29.21 U$4.K2 20.95,29.84 21.59,30.48 21.59,34.29 29.21,34.29 34.92,28.57 E2.2 36.2,28.57 41.27,33.66 41.27,36.2 41.91,36.83 44.45,36.83 45.72,38.1 v47.62,38.1 | 59.69,34.29 60.33,33.66 60.33,31.11 65.41,26.04 E8.1 | 59.69,34.29 54.61,34.29 v54.61,38.1 | v63.5,39.37 62.23,38.1 62.23,36.83 59.69,34.29
  Bottom 0.254: E14.6 95.25,38.1 93.98,39.37 76.2,39.37 74.93,38.1 E11.9 72.39,38.1 68.58,38.1 67.31,39.37 v63.5,39.37 | v54.61,38.1 52.07,38.1 E5.6 49.53,38.1 v47.62,38.1
K2  (via drill 0.61)
  Top 0.254: v69.22,33.02 71.12,31.11 v71.12,27.94 | 41.27,22.23 39.37,24.13 v39.37,30.48 | 41.27,22.23 42.55,20.95 E4.8 | 41.27,22.23 38.73,19.68 38.73,15.88 36.83,13.97 34.29,13.97 33.66,13.34 33.66,8.89 36.83,8.89 37.47,8.26 37.47,3.81 82.55,3.81 85.09,6.35 85.09,21.59 81.92,24.77 E11.1
  Bottom 0.254: 83.82,26.67 82.55,25.4 E11.1 | 83.82,26.67 93.98,26.67 95.25,25.4 E14.1 | v69.22,33.02 67.31,33.02 E8.4 | v71.12,27.94 72.39,26.67 83.82,26.67 | U$1.K2 13.97,29.84 17.14,29.84 U$4.K1 18.41,30.48 20.95,30.48 22.23,29.21 29.21,29.21 29.84,29.84 33.66,29.84 34.29,30.48 E2.3 36.83,30.48 v39.37,30.48
L1  (via drill 0.61)
  Top 0.254: E2.5 36.2,36.2 38.1,38.1 38.1,39.37 44.45,39.37 46.35,41.27 46.35,42.55 49.53,45.72 E6.1 51.44,45.09 52.7,43.81 v52.7,31.75 | v73.03,23.5 73.03,24.13 74.93,24.13 78.11,27.3 78.11,36.2 74.3,40.01 E11.8 | v71.12,22.86 67.31,19.05 62.23,19.05 v62.23,26.67 | U$1.L1 13.97,32.38 19.68,32.38 U$4.L2
  Bottom 0.254: U$4.L2 20.95,33.66 21.59,34.29 33.02,34.29 34.29,35.56 E2.5 | 62.23,29.21 56.52,29.21 53.98,31.75 v52.7,31.75 | 62.23,29.21 63.5,29.21 64.77,27.94 E8.2 | v73.03,23.5 72.39,22.86 v71.12,22.86 | 62.23,29.21 v62.23,26.67
L2  (via drill 0.61)
  Top 0.254: v63.5,30.48 64.14,31.11 64.14,33.66 65.41,34.92 E8.5
  Bottom 0.254: U$1.L2 13.97,33.66 17.14,33.66 U$4.L1 18.41,33.66 18.41,31.75 29.21,31.75 30.48,33.02 34.29,33.02 E2.4 36.83,33.02 39.37,35.56 41.91,35.56 E5.10 44.45,35.56 45.72,35.56 46.99,36.83 59.69,36.83 60.96,35.56 64.77,35.56 E8.5 | E14.2 95.25,27.94 93.98,29.21 87.63,29.21 87,28.57 83.19,28.57 82.55,27.94 E11.2 80.01,27.94 79.38,28.57 75.56,28.57 74.93,29.21 70.48,29.21 69.22,27.94 68.58,27.94 67.31,29.21 64.77,29.21 v63.5,30.48
M1  (via drill 0.61)
  Top 0.254: E12.13 74.93,48.26 78.11,48.26 79.38,49.53 87.63,49.53 87.63,50.8 E15.12 | E2.6 36.2,38.73 37.47,40.01 37.47,41.91 45.09,41.91 45.72,42.55 45.72,43.18 50.16,47.62 E6.2 51.44,47.62 53.34,45.72 53.34,38.1 53.98,37.47 v53.98,30.48 | v68.58,48.26 67.31,46.99 v61.59,46.99 | U$1.M1 13.97,35.56 19.68,35.56 U$4.M2
  Bottom 0.254: U$4.M2 20.95,36.2 21.59,36.83 31.75,36.83 33.02,38.1 34.29,38.1 E2.6 | v53.98,30.48 55.88,28.57 56.52,28.57 57.15,27.94 E8.13 | v68.58,48.26 72.39,48.26 E12.13 | v61.59,46.99 53.34,46.99 52.07,48.26 E6.2
M2  (via drill 0.61)
  Top 0.254: E14.3 95.25,30.48 91.44,34.29 81.92,34.29 81.92,33.66 E11.4 | v76.2,33.02 74.93,34.29 69.85,34.29 69.85,35.56 67.31,38.1 E8.6
  Bottom 0.254: U$1.M2 13.97,36.2 17.14,36.2 U$4.M1 18.41,37.47 26.04,37.47 26.67,38.1 E2.9 29.21,38.1 30.48,39.37 40.64,39.37 41.91,38.1 E5.9 44.45,38.1 46.35,38.1 47.62,39.37 59.69,39.37 60.96,38.1 64.77,38.1 E8.6 | v76.2,33.02 80.01,33.02 E11.4
N1  (via drill 0.61)
  Top 0.254: v62.23,30.48 63.5,31.75 63.5,38.1 64.77,39.37 v68.58,39.37 | v71.12,39.37 69.85,40.64 69.85,45.72 71.75,47.62 71.75,48.9 73.03,50.16 E12.12 74.3,51.44 74.3,52.07 83.19,52.07 84.45,53.34 87.63,53.34 E15.11 | v48.26,48.26 50.16,50.16 E6.3 | U$1.N1 13.97,39.37 19.68,39.37 U$4.N2 20.95,40.01 21.59,40.64 21.59,46.35 v22.23,46.99 | v69.22,52.07 v70.48,50.8 | v60.96,52.7 60.33,52.7 59.69,52.07 55.88,52.07 v55.88,50.8
  Bottom 0.254: v62.23,30.48 59.69,30.48 E8.12 | v71.12,39.37 v68.58,39.37 | v48.26,48.26 47.62,48.26 46.35,46.99 38.1,46.99 36.83,45.72 E3.1 34.29,45.72 33.02,46.99 v22.23,46.99 | v70.48,50.8 72.39,50.8 E12.12 | v69.22,52.07 61.59,52.07 v60.96,52.7 | v55.88,50.8 52.07,50.8 E6.3
N2  (via drill 0.61)
  Top 0.254: v47.62,41.27 48.9,40.01 48.9,29.21 53.98,29.21 55.24,30.48 55.24,33.02 57.15,33.02 E8.11
  Bottom 0.254: 92.71,31.75 93.98,31.75 95.25,33.02 E14.4 | 92.71,31.75 60.96,31.75 59.69,33.02 E8.11 | 92.71,31.75 90.17,34.29 83.82,34.29 82.55,35.56 E11.5 | U$1.N2 13.97,40.01 17.14,40.01 U$4.N1 18.41,40.64 26.67,40.64 E2.8 29.21,40.64 29.84,40.64 31.11,41.91 40.64,41.91 41.91,40.64 E5.8 44.45,40.64 46.99,40.64 v47.62,41.27
P1  (via drill 0.61)
  Top 0.254: E9.1 67.31,45.72 71.75,50.16 71.75,53.98 73.03,55.24 E12.10 74.3,55.24 74.3,54.61 90.81,54.61 92.08,55.88 95.25,55.88 E15.5 | U$4.P2 19.68,41.91 13.97,41.91 U$1.P1 | v31.11,43.18 31.11,43.81 34.92,47.62 E3.2 36.2,48.9 37.47,50.16 37.47,52.07 44.45,52.07 v45.72,53.34 | v53.98,55.24 v55.88,57.15
  Bottom 0.254: v31.11,43.18 29.84,41.91 20.95,41.91 U$4.P2 | v45.72,53.34 49.53,53.34 E6.4 52.07,53.34 v53.98,55.24 | v55.88,57.15 60.96,57.15 63.5,54.61 67.31,54.61 67.94,55.24 71.75,55.24 72.39,55.88 E12.10
P2  (via drill 0.61)
  Top 0.254: v60.96,36.83 59.69,35.56 E8.10 | E14.8 87.63,40.64 84.45,40.64 84.45,40.01 82.55,38.1 E11.6 | E3.3 34.29,50.8 31.11,53.98 29.84,53.98 29.84,50.16 29.21,49.53 26.04,49.53 v26.04,43.18 26.04,36.83 v33.02,36.83 | v68.58,35.56 67.94,34.92 67.94,24.13 65.41,21.59 v63.5,21.59 | v47.62,20.95 45.72,22.86 v45.72,36.83
  Bottom 0.254: 68.58,36.83 78.74,36.83 80.01,38.1 E11.6 | 68.58,36.83 v60.96,36.83 | E6.13 41.91,48.26 41.27,47.62 37.47,47.62 36.83,46.99 34.29,46.99 32.38,48.9 32.38,50.8 34.29,50.8 E3.3 | U$1.P2 13.97,42.55 17.14,42.55 U$4.P1 18.41,43.18 v26.04,43.18 | v68.58,35.56 68.58,36.83 | v63.5,21.59 60.96,19.05 49.53,19.05 v47.62,20.95 | v33.02,36.83 v45.72,36.83
R1  (via drill 0.61)
  Top 0.254: U$1.R1 13.97,45.09 19.68,45.09 U$4.R2 19.68,46.35 19.05,46.99 19.05,55.24 19.68,55.88 20.95,55.88 21.59,56.52 21.59,57.78 23.5,59.69 33.66,59.69 33.66,57.78 34.92,56.52 E3.5 36.83,55.88 40.64,55.88 41.91,57.15 46.99,57.15 v46.99,55.88 | E12.9 73.03,57.78 71.12,55.88 71.12,53.98 69.85,53.98 67.94,52.07 67.94,50.16 66.67,48.9 E9.2 64.77,48.26 61.59,48.26 60.33,46.99 57.15,46.99 53.98,50.16 53.98,52.7 51.44,55.24 E6.5
  Bottom 0.254: v46.99,55.88 49.53,55.88 E6.5 | E15.6 95.25,58.42 93.98,57.15 78.11,57.15 76.83,58.42 74.93,58.42 E12.9
R2  (via drill 0.61)
  Top 0.254: v62.23,42.55 62.23,41.91 59.05,38.73 E8.9 | v46.35,45.09 46.35,47.62 43.81,50.16 E6.12
  Bottom 0.254: U$1.R2 13.97,46.35 17.14,46.35 U$4.R1 18.41,46.35 18.41,44.45 46.99,44.45 | E3.4 36.83,53.34 39.37,50.8 41.91,50.8 E6.12 | 64.14,44.45 v62.23,42.55 | 64.14,44.45 75.56,44.45 76.83,45.72 80.01,45.72 E12.1 82.55,45.72 83.82,46.99 93.98,46.99 95.25,45.72 E15.1 | 46.99,44.45 v46.35,45.09 | 46.99,44.45 64.14,44.45
S1  (via drill 0.61)
  Top 0.254: v15.88,48.26 13.97,48.26 U$1.S1 | 64.77,54.61 59.05,48.9 E9.13 | 64.77,54.61 70.48,54.61 70.48,57.78 73.03,60.33 E12.8 | v55.88,54.61 64.77,54.61 | v22.23,52.07 22.23,50.16 20.95,48.9 U$4.S2
  Bottom 0.254: v15.88,48.26 19.68,48.26 U$4.S2 | v55.88,54.61 52.07,58.42 E6.6 49.53,58.42 46.99,58.42 45.72,57.15 41.91,57.15 41.27,57.78 37.47,57.78 36.83,58.42 E3.6 34.29,58.42 31.11,58.42 29.84,57.15 26.67,57.15 26.04,56.52 26.04,55.88 v22.23,52.07
S2  (via drill 0.61)
  Top 0.254: E12.2 82.55,48.26 85.72,48.26 87,46.99 95.25,46.99 95.25,48.26 E15.2 | 48.26,52.07 46.99,52.07 46.99,53.34 45.72,54.61 43.81,54.61 43.81,53.98 E6.11 | 48.26,52.07 52.07,52.07 52.7,51.44 52.7,50.16 53.98,48.9 53.98,45.09 57.78,41.27 E8.8 59.69,40.64 60.96,41.91 60.96,44.45 67.31,44.45 v69.85,46.99 | 48.26,52.07 48.26,55.88 47.62,56.52 47.62,62.23 23.5,62.23 19.05,57.78 19.05,57.15 17.14,57.15 16.51,56.52 16.51,55.24 17.14,54.61 16.51,53.98 16.51,52.7 17.14,52.07 17.14,50.16 U$4.S1
  Bottom 0.254: E3.13 26.67,48.26 25.4,49.53 18.41,49.53 U$4.S1 17.14,49.53 13.97,49.53 U$1.S2 | v69.85,46.99 78.74,46.99 80.01,48.26 E12.2
T2  (via drill 0.61)
  Top 0.254: v40.64,54.61 41.91,55.88 E6.10
  Bottom 0.254: 78.74,52.07 70.48,52.07 69.22,50.8 67.31,50.8 E9.3 64.77,50.8 64.14,51.44 60.33,51.44 59.69,52.07 41.91,52.07 39.37,54.61 | 78.74,52.07 80.01,53.34 E12.4 | 78.74,52.07 93.98,52.07 95.25,50.8 E15.3 | U$4.T1 17.14,53.34 14.61,53.34 13.97,52.7 U$1.T2 13.97,51.44 14.61,50.8 26.67,50.8 E3.12 29.21,50.8 30.48,50.8 34.29,54.61 39.37,54.61 | 39.37,54.61 v40.64,54.61
U1  (via drill 0.61)
  Top 0.254: U$4.U2 20.95,54.61 26.67,54.61 26.67,55.88 E3.10 | v15.88,54.61 13.97,54.61 U$1.U1 | v31.11,52.7 33.66,50.16 v33.66,49.53
  Bottom 0.254: v15.88,54.61 19.68,54.61 U$4.U2 | 60.96,49.53 59.69,50.8 E9.12 | 60.96,49.53 98.42,49.53 101.6,52.7 R5.1 101.6,53.98 101.6,55.24 R4.2 | v31.11,52.7 28.57,55.24 E3.10 | v33.66,49.53 60.96,49.53
U2  (via drill 0.61)
  Top 0.254: v22.23,55.88 22.23,57.15 23.5,58.42 26.67,58.42 E3.9
  Bottom 0.254: U$1.U2 13.97,55.88 17.14,55.88 U$4.U1 18.41,55.88 v22.23,55.88 | E3.9 29.21,58.42 29.84,59.05 33.66,59.05 34.29,59.69 40.64,59.69 41.91,58.42 E6.9 44.45,58.42 45.09,59.05 48.9,59.05 49.53,59.69 52.07,59.69 57.15,54.61 62.23,54.61 63.5,53.34 64.77,53.34 E9.4 67.31,53.34 68.58,54.61 78.74,54.61 | 78.74,54.61 80.01,55.88 E12.5 | 78.74,54.61 93.98,54.61 95.25,53.34 E15.4
V1  (via drill 0.61)
  Top 0.254: v15.88,57.15 13.97,57.15 13.97,57.78 U$1.V1 | 29.21,57.15 29.84,56.52 29.84,55.24 28.57,53.98 E3.11 | v23.5,57.15 29.21,57.15 | v48.9,57.15 48.9,62.23 60.96,62.23 64.77,58.42 E9.6 | 29.21,57.15 v31.11,57.15
  Bottom 0.254: E9.6 67.31,58.42 68.58,59.69 99.69,59.69 100.97,60.96 R7.2 101.6,60.33 101.6,59.05 R6.1 | v15.88,57.15 19.68,57.15 U$4.V2 20.95,57.15 v23.5,57.15 | v48.9,57.15 46.99,57.15 44.45,54.61 41.91,54.61 39.37,57.15 v31.11,57.15
V2
  Top 0.254: E12.6 82.55,58.42 85.72,58.42 85.72,59.05 87.63,60.96 E15.8
  Bottom 0.254: 68.58,60.96 69.85,62.23 86.36,62.23 87.63,60.96 E15.8 | 68.58,60.96 67.31,59.69 64.77,59.69 64.14,59.05 64.14,57.78 65.41,56.52 E9.5 | U$1.V2 13.97,58.42 17.14,58.42 U$4.V1 18.41,59.05 19.68,59.05 20.95,60.33 26.04,60.33 26.67,60.96 E3.8 29.21,60.96 30.48,62.23 40.64,62.23 | 40.64,62.23 41.91,60.96 E6.8 | 68.58,60.96 67.31,62.23 40.64,62.23
VCC
  Top 0.381: C9.1 59.69,43.81 59.05,44.45 59.05,45.09 E9.14 | E3.14 28.57,45.09 28.57,44.45 29.21,43.81 C3.1 29.21,42.55 30.48,41.27 33.02,41.27 33.02,43.81 33.66,44.45 41.91,44.45 41.91,45.72 E6.14 43.81,45.09 43.81,44.45 44.45,43.81 C6.1 | E12.14 74.3,45.09 74.93,44.45 74.93,43.81 C12.1 74.93,42.55 78.74,38.73 78.74,26.04 75.56,22.86 C11.1
  Bottom 0.381: E12.14 72.39,45.72 68.58,45.72 67.31,46.99 63.5,46.99 62.23,45.72 59.69,45.72 E9.14 57.15,45.72 56.52,46.35 52.7,46.35 52.07,46.99 47.62,46.99 46.99,46.35 43.81,46.35 E6.14 | R6.2 111.12,58.42 110.49,58.42 110.49,55.24 111.76,53.98 R5.2 111.12,53.34 102.23,44.45 89.53,44.45 | C12.1 75.56,43.18 76.83,44.45 86.36,44.45 87.63,45.72 E15.14 88.9,45.09 89.53,44.45 | 89.53,44.45 90.17,43.81 C15.1 | 89.53,24.13 89.53,23.5 90.17,23.5 C14.1 90.81,22.86 92.08,24.13 95.89,24.13 98.42,21.59 98.42,3.81 89.53,3.81 | 89.53,24.13 89.53,24.77 E14.14 | 89.53,24.13 76.83,24.13 75.56,22.86 C11.1 74.93,23.5 74.3,23.5 74.3,24.77 E11.14 72.39,25.4 71.12,24.13 62.87,24.13 61.59,22.86 60.33,22.86 C8.1 59.69,23.5 59.05,23.5 59.05,24.77 E8.14 57.15,25.4 55.88,24.13 43.81,24.13 | E2.14 28.57,24.77 28.57,23.5 29.21,23.5 C2.1 29.84,22.86 31.11,24.13 43.81,24.13 | 43.81,24.13 43.81,23.5 44.45,23.5 C5.1 | 43.81,24.13 43.81,24.77 E5.14 | 89.53,3.81 89.53,3.17 90.17,3.17 C13.1 | 89.53,3.81 89.53,4.45 E13.14 87.63,5.08 86.36,3.81 74.3,3.81 | 74.3,3.81 74.3,3.17 74.93,3.17 C10.1 | 74.3,3.81 74.3,4.45 E10.14 72.39,5.08 71.12,3.81 59.05,3.81 | 59.05,3.81 59.05,3.17 59.69,3.17 C7.1 | 59.05,3.81 59.05,4.45 E7.14 57.15,5.08 55.88,3.81 43.81,3.81 | 43.81,3.81 43.81,3.17 44.45,3.17 C4.1 | 43.81,3.81 43.81,4.45 E4.14 41.91,5.08 40.64,3.81 28.57,3.81 | 28.57,3.81 28.57,3.17 29.21,3.17 C1.1 | 28.57,3.81 28.57,4.45 E1.14 26.67,5.08 18.41,5.08 U$4.A1 17.14,4.45 14.61,4.45 U$1.A2

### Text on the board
tNames: M111 | M113 | M115 | M117 | M119 | M111 or M115. | Fill Only One Row. | Install Resistors Unless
